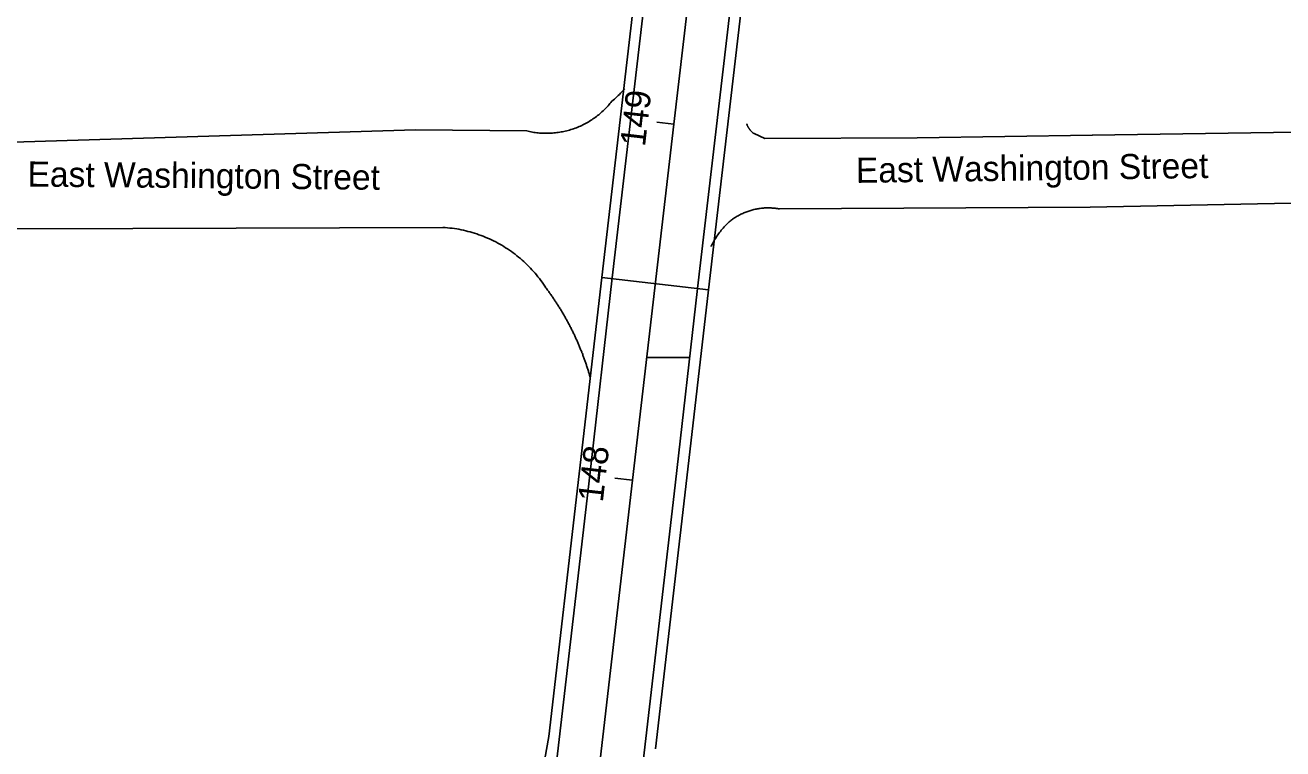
# Model space of a CAD drawing. Extents: x 2318076 to 2324211, y 613525 to 629939.
# Drawn here: x 2320544.3 to 2320895.3, y 629287.5 to 629489.4 of the extents above; entities that cross this region are included whole.
import ezdxf

# ---------------------------------------------------------------- set-up
doc = ezdxf.new("R2010")
doc.units = 0
for name, color, linetype in [('GE_P_CL_50', 7, 'Continuous'), ('PV_P_EOP', 7, 'Continuous'), ('PV_P_Shoulder', 7, 'Continuous'), ('PV_X_Shoulder', 7, 'Continuous'), ('RS_Raster1', 7, 'Continuous'), ('SC_Scratch1', 7, 'Continuous')]:
    doc.layers.add(name, color=color, linetype=linetype)

msp = doc.modelspace()

# ---------------------------------------------------------------- linework, layer by layer
at = {"layer": 'GE_P_CL_50'}
for p, q in [((2320725.26, 629461.78), (2320720.57, 629462.32)), ((2320713.75, 629362.45), (2320708.79, 629363.02))]:
    msp.add_line(p, q, dxfattribs=at)
msp.add_lwpolyline([(2320485.22, 627375.57), (2320502.11, 627520.92), (2320519.22, 627676.47), (2320531.82, 627783.89), (2320546.8, 627927.12), (2320554.45, 627991.34), (2320572.51, 628138.41), (2320649.52, 628804.84), (2320678.77, 629064.5), (2320690.76, 629163.78), (2320713.75, 629362.45), (2320725.26, 629461.78), (2320736.97, 629561.09), (2320748.4, 629660.43), (2320759.09, 629759.86), (2320769.62, 629859.3), (2320777.51, 629931.12), (2320778.25, 629937.84)], dxfattribs=at)
at = {"layer": 'PV_P_EOP'}
for p, q in [((2320747.44, 629459.26), (2320747.75, 629459.13)), ((2320705.21, 629419), (2320735, 629415.55))]:
    msp.add_line(p, q, dxfattribs=at)
for points in [[(2320707.99, 629468.12), (2320708.36, 629468.42), (2320708.72, 629468.73), (2320709.08, 629469.05), (2320709.43, 629469.37), (2320709.78, 629469.7), (2320710.12, 629470.04), (2320710.45, 629470.38), (2320710.78, 629470.72), (2320711.1, 629471.08), (2320711.42, 629471.43), (2320711.58, 629471.62)], [(2320679.85, 629173.88), (2320701.83, 629363.83), (2320708.13, 629418.9), (2320708.13, 629418.9)], [(2320704.21, 629175.59), (2320725.67, 629361.07), (2320731.95, 629415.91), (2320731.95, 629415.91)]]:
    msp.add_lwpolyline(points, dxfattribs=at)
at = {"layer": 'PV_P_Shoulder'}
msp.add_line((2320669.97, 629175.43), (2320690.38, 629290.93), dxfattribs=at)
for points in [[(2320690.38, 629290.93), (2320698.85, 629364.17), (2320705.21, 629419), (2320705.21, 629419)], [(2320720.18, 629287.5), (2320728.65, 629360.72), (2320735.01, 629415.55), (2320735.01, 629415.55)]]:
    msp.add_lwpolyline(points, dxfattribs=at)
at = {"layer": 'PV_X_Shoulder'}
for points in [[(2320705.21, 629419), (2320733.49, 629662.09), (2320744.17, 629761.45), (2320754.71, 629860.91), (2320762.6, 629932.76), (2320763.34, 629939.48)], [(2320735.01, 629415.55), (2320763.31, 629658.77), (2320774, 629758.27), (2320784.54, 629857.69), (2320792.42, 629929.48), (2320793.16, 629936.2)]]:
    msp.add_lwpolyline(points, dxfattribs=at)
at = {"layer": 'RS_Raster1'}
msp.add_line((2320841.5, 629438.56), (2320754.79, 629438.1), dxfattribs=at)
for points in [[(2320708.13, 629418.9), (2320736.47, 629661.76), (2320747.15, 629761.13), (2320757.69, 629860.59), (2320765.58, 629932.43), (2320766.32, 629939.15)], [(2320731.95, 629415.91), (2320760.33, 629659.11), (2320771.02, 629758.59), (2320781.55, 629858.02), (2320789.44, 629929.81), (2320790.18, 629936.53)], [(2322566.94, 629479.72), (2322351.65, 629476.68), (2322140.39, 629474.14), (2321926.11, 629471.53), (2321678.25, 629469.05), (2321429.71, 629465.5), (2321192.6, 629463.24), (2320949.44, 629460.28), (2320842.07, 629458.72)], [(2320707.99, 629468.12), (2320708.36, 629468.42), (2320708.72, 629468.73), (2320709.08, 629469.05), (2320709.43, 629469.37), (2320709.78, 629469.7), (2320710.12, 629470.04), (2320710.45, 629470.38), (2320710.78, 629470.72), (2320711.1, 629471.08), (2320711.42, 629471.43), (2320711.58, 629471.62)], [(2320684.27, 629459.85), (2320684.66, 629459.76), (2320685.05, 629459.67), (2320685.45, 629459.59), (2320685.84, 629459.52), (2320686.24, 629459.46), (2320686.64, 629459.4), (2320687.04, 629459.35), (2320687.44, 629459.31), (2320687.84, 629459.27), (2320688.24, 629459.24), (2320688.64, 629459.22), (2320689.04, 629459.2), (2320689.44, 629459.19), (2320689.84, 629459.19), (2320690.25, 629459.2), (2320690.65, 629459.21), (2320691.05, 629459.23), (2320691.45, 629459.26), (2320691.85, 629459.29), (2320692.25, 629459.33), (2320692.65, 629459.38), (2320693.05, 629459.43), (2320693.45, 629459.49), (2320693.84, 629459.56), (2320694.24, 629459.64), (2320694.63, 629459.72), (2320695.02, 629459.81), (2320695.42, 629459.9), (2320695.8, 629460), (2320696.19, 629460.11), (2320696.58, 629460.23), (2320696.96, 629460.35), (2320697.34, 629460.48), (2320697.72, 629460.62), (2320698.1, 629460.76), (2320698.47, 629460.91), (2320698.84, 629461.06), (2320699.21, 629461.23), (2320699.58, 629461.39), (2320699.94, 629461.57), (2320700.3, 629461.75), (2320700.66, 629461.94), (2320701.01, 629462.13), (2320701.36, 629462.33), (2320701.7, 629462.53), (2320702.05, 629462.75), (2320702.39, 629462.96), (2320702.72, 629463.19), (2320703.05, 629463.41), (2320703.38, 629463.65), (2320703.7, 629463.89), (2320704.02, 629464.14), (2320704.34, 629464.39), (2320704.65, 629464.64), (2320704.95, 629464.91), (2320705.25, 629465.17), (2320705.55, 629465.45), (2320705.84, 629465.72), (2320706.13, 629466.01), (2320706.41, 629466.29), (2320706.69, 629466.59), (2320706.96, 629466.88), (2320707.22, 629467.19), (2320707.48, 629467.49), (2320707.74, 629467.8), (2320707.99, 629468.12)], [(2319842.85, 629447.56), (2319958.85, 629449.26), (2320053.94, 629450.97), (2320137.26, 629451.41), (2320227.99, 629452.77), (2320303.35, 629453.56), (2320382.52, 629453.53), (2320492.19, 629455.24), (2320653.24, 629460.17), (2320684.27, 629459.85)], [(2320745.65, 629461.85), (2320745.67, 629461.77), (2320745.7, 629461.69), (2320745.73, 629461.62), (2320745.75, 629461.54), (2320745.78, 629461.46), (2320745.81, 629461.39), (2320745.85, 629461.31), (2320745.88, 629461.24), (2320745.91, 629461.16), (2320745.95, 629461.09), (2320745.99, 629461.02), (2320746.02, 629460.94), (2320746.06, 629460.87), (2320746.1, 629460.8), (2320746.15, 629460.73), (2320746.19, 629460.66), (2320746.23, 629460.59), (2320746.28, 629460.53), (2320746.32, 629460.46), (2320746.37, 629460.39), (2320746.42, 629460.33), (2320746.47, 629460.26), (2320746.52, 629460.2), (2320746.57, 629460.13), (2320746.63, 629460.07), (2320746.68, 629460.01), (2320746.74, 629459.95), (2320746.79, 629459.89), (2320746.85, 629459.83), (2320747.44, 629459.26)], [(2320747.75, 629459.13), (2320750.68, 629457.71), (2320793.25, 629457.96), (2320842.1, 629458.72)], [(2322565.73, 629458.91), (2322455.24, 629458), (2322329.32, 629458.43), (2322171.68, 629455.87), (2322013.49, 629454.1), (2321831.46, 629451.91), (2321642.26, 629450.16), (2321452.49, 629446.74), (2321289.49, 629445.15), (2321104.08, 629442.45), (2320902.23, 629439.77), (2320841.5, 629438.56)], [(2320754.79, 629438.1), (2320754.5, 629438.15), (2320754.2, 629438.2), (2320753.9, 629438.24), (2320753.61, 629438.28), (2320753.31, 629438.31), (2320753.01, 629438.33), (2320752.71, 629438.35), (2320752.42, 629438.37), (2320752.12, 629438.38), (2320751.82, 629438.39), (2320751.52, 629438.39), (2320751.22, 629438.38), (2320750.92, 629438.37), (2320750.62, 629438.36), (2320750.33, 629438.34), (2320750.03, 629438.31), (2320749.73, 629438.28), (2320749.43, 629438.24), (2320749.14, 629438.2), (2320748.84, 629438.16), (2320748.55, 629438.11), (2320748.26, 629438.05), (2320747.96, 629437.99), (2320747.67, 629437.92), (2320747.38, 629437.85), (2320747.09, 629437.78), (2320746.8, 629437.7), (2320746.52, 629437.61), (2320746.23, 629437.52), (2320745.95, 629437.42), (2320745.67, 629437.32), (2320745.39, 629437.22), (2320745.11, 629437.11), (2320744.84, 629436.99), (2320744.56, 629436.87), (2320744.29, 629436.75), (2320744.02, 629436.62), (2320743.75, 629436.49), (2320743.49, 629436.35), (2320743.23, 629436.21), (2320742.97, 629436.06), (2320742.71, 629435.91), (2320742.45, 629435.75), (2320742.2, 629435.59), (2320741.95, 629435.43), (2320741.71, 629435.26), (2320741.46, 629435.08), (2320741.22, 629434.91), (2320740.98, 629434.73), (2320740.75, 629434.54)], [(2320660.88, 629432.95), (2320574.31, 629432.6), (2320440.43, 629432.35), (2320286.81, 629430.91), (2320140.72, 629428.3), (2319969.44, 629425.44), (2319838.12, 629424.35)], [(2320689.62, 629416.06), (2320689.27, 629416.6), (2320688.91, 629417.13), (2320688.54, 629417.65), (2320688.16, 629418.17), (2320687.78, 629418.68), (2320687.38, 629419.19), (2320686.98, 629419.68), (2320686.56, 629420.17), (2320686.14, 629420.66), (2320685.71, 629421.13), (2320685.28, 629421.6), (2320684.83, 629422.06), (2320684.38, 629422.51), (2320683.91, 629422.96), (2320683.45, 629423.39), (2320682.97, 629423.82), (2320682.48, 629424.24), (2320681.99, 629424.65), (2320681.49, 629425.06), (2320680.99, 629425.45), (2320680.48, 629425.84), (2320679.96, 629426.21), (2320679.43, 629426.58), (2320678.9, 629426.94), (2320678.36, 629427.28), (2320677.82, 629427.62), (2320677.27, 629427.95), (2320676.72, 629428.27), (2320676.15, 629428.58), (2320675.59, 629428.88), (2320675.02, 629429.17), (2320674.44, 629429.45), (2320673.86, 629429.72), (2320673.28, 629429.98), (2320672.69, 629430.23), (2320672.09, 629430.47), (2320671.49, 629430.7), (2320670.89, 629430.92), (2320670.29, 629431.13), (2320669.68, 629431.33), (2320669.06, 629431.51), (2320668.45, 629431.69), (2320667.83, 629431.85), (2320667.21, 629432.01), (2320666.58, 629432.15), (2320665.96, 629432.29), (2320665.33, 629432.41), (2320664.7, 629432.52), (2320664.06, 629432.62), (2320663.43, 629432.71), (2320662.79, 629432.78), (2320662.16, 629432.85), (2320661.52, 629432.91), (2320660.88, 629432.95)], [(2320740.75, 629434.54), (2320740.46, 629434.26), (2320740.17, 629433.97), (2320739.88, 629433.68), (2320739.61, 629433.38), (2320739.33, 629433.08), (2320739.07, 629432.77), (2320738.8, 629432.46), (2320738.55, 629432.15), (2320738.29, 629431.83), (2320738.05, 629431.5), (2320737.81, 629431.18), (2320737.57, 629430.84), (2320737.34, 629430.51), (2320737.12, 629430.17), (2320736.9, 629429.82), (2320736.69, 629429.47), (2320736.49, 629429.12), (2320736.29, 629428.77), (2320736.1, 629428.41), (2320735.91, 629428.05), (2320735.73, 629427.68), (2320735.71, 629427.64)], [(2320701.97, 629391.11), (2320701.95, 629391.16), (2320701.88, 629391.41), (2320701.81, 629391.66), (2320701.74, 629391.9), (2320701.67, 629392.15), (2320701.59, 629392.4), (2320701.52, 629392.64), (2320701.44, 629392.89), (2320701.37, 629393.13), (2320701.29, 629393.38), (2320701.21, 629393.62), (2320701.13, 629393.86), (2320701.05, 629394.11), (2320700.97, 629394.35), (2320700.89, 629394.6), (2320700.81, 629394.84), (2320700.73, 629395.08), (2320700.64, 629395.32), (2320700.56, 629395.57), (2320700.48, 629395.81), (2320700.39, 629396.05), (2320700.3, 629396.29), (2320700.22, 629396.53), (2320700.13, 629396.77), (2320700.04, 629397.01), (2320699.95, 629397.25), (2320699.86, 629397.49), (2320699.77, 629397.73), (2320699.67, 629397.97), (2320699.58, 629398.21), (2320699.49, 629398.45), (2320699.39, 629398.69), (2320699.29, 629398.93), (2320699.2, 629399.17), (2320699.1, 629399.4), (2320699, 629399.64), (2320698.9, 629399.88), (2320698.8, 629400.11), (2320698.7, 629400.35), (2320698.6, 629400.58), (2320698.5, 629400.82), (2320698.4, 629401.06), (2320698.29, 629401.29), (2320698.19, 629401.52), (2320698.08, 629401.76), (2320697.98, 629401.99), (2320697.87, 629402.22), (2320697.76, 629402.46), (2320697.66, 629402.69), (2320697.55, 629402.92), (2320697.44, 629403.15), (2320697.33, 629403.39), (2320697.21, 629403.62), (2320697.1, 629403.85), (2320696.99, 629404.08), (2320696.87, 629404.31), (2320696.76, 629404.54), (2320696.64, 629404.77), (2320696.53, 629404.99), (2320696.41, 629405.22), (2320696.29, 629405.45), (2320696.18, 629405.68), (2320696.06, 629405.9), (2320695.94, 629406.13), (2320695.82, 629406.36), (2320695.69, 629406.58), (2320695.57, 629406.81), (2320695.45, 629407.03), (2320695.33, 629407.26), (2320695.2, 629407.48), (2320695.08, 629407.71), (2320694.95, 629407.93), (2320694.82, 629408.15), (2320694.69, 629408.37), (2320694.57, 629408.6), (2320694.44, 629408.82), (2320694.31, 629409.04), (2320694.18, 629409.26), (2320694.05, 629409.48), (2320693.91, 629409.7), (2320693.78, 629409.92), (2320693.65, 629410.14), (2320693.51, 629410.35), (2320693.38, 629410.57), (2320693.24, 629410.79), (2320693.11, 629411.01), (2320692.97, 629411.22), (2320692.83, 629411.44), (2320692.69, 629411.65), (2320692.55, 629411.87), (2320692.41, 629412.08), (2320692.27, 629412.3), (2320692.13, 629412.51), (2320691.99, 629412.72), (2320691.85, 629412.94), (2320691.7, 629413.15), (2320691.56, 629413.36), (2320691.41, 629413.57), (2320691.27, 629413.78), (2320691.12, 629413.99), (2320690.98, 629414.2), (2320690.83, 629414.41), (2320690.68, 629414.62), (2320690.53, 629414.82), (2320690.38, 629415.03), (2320690.23, 629415.24), (2320690.08, 629415.44), (2320689.93, 629415.65), (2320689.77, 629415.86), (2320689.62, 629416.06)]]:
    msp.add_lwpolyline(points, dxfattribs=at)
at = {"layer": 'SC_Scratch1'}
msp.add_line((2320717.72, 629396.69), (2320729.89, 629396.69), dxfattribs=at)

# ---------------------------------------------------------------- texts
at = {"layer": 'GE_P_CL_50'}
for s, rotation, p in [('149', 83.3814, (2320717.24, 629455.3)), ('East Washington Street', 0.7948, (2320776.16, 629445.36)), ('East Washington Street', 359.4616, (2320544.92, 629444.35)), ('148', 83.4076, (2320705.47, 629356.11))]:
    msp.add_text(s, height=7, rotation=rotation, dxfattribs=at).set_placement(p)

doc.saveas('drawing.dxf')
